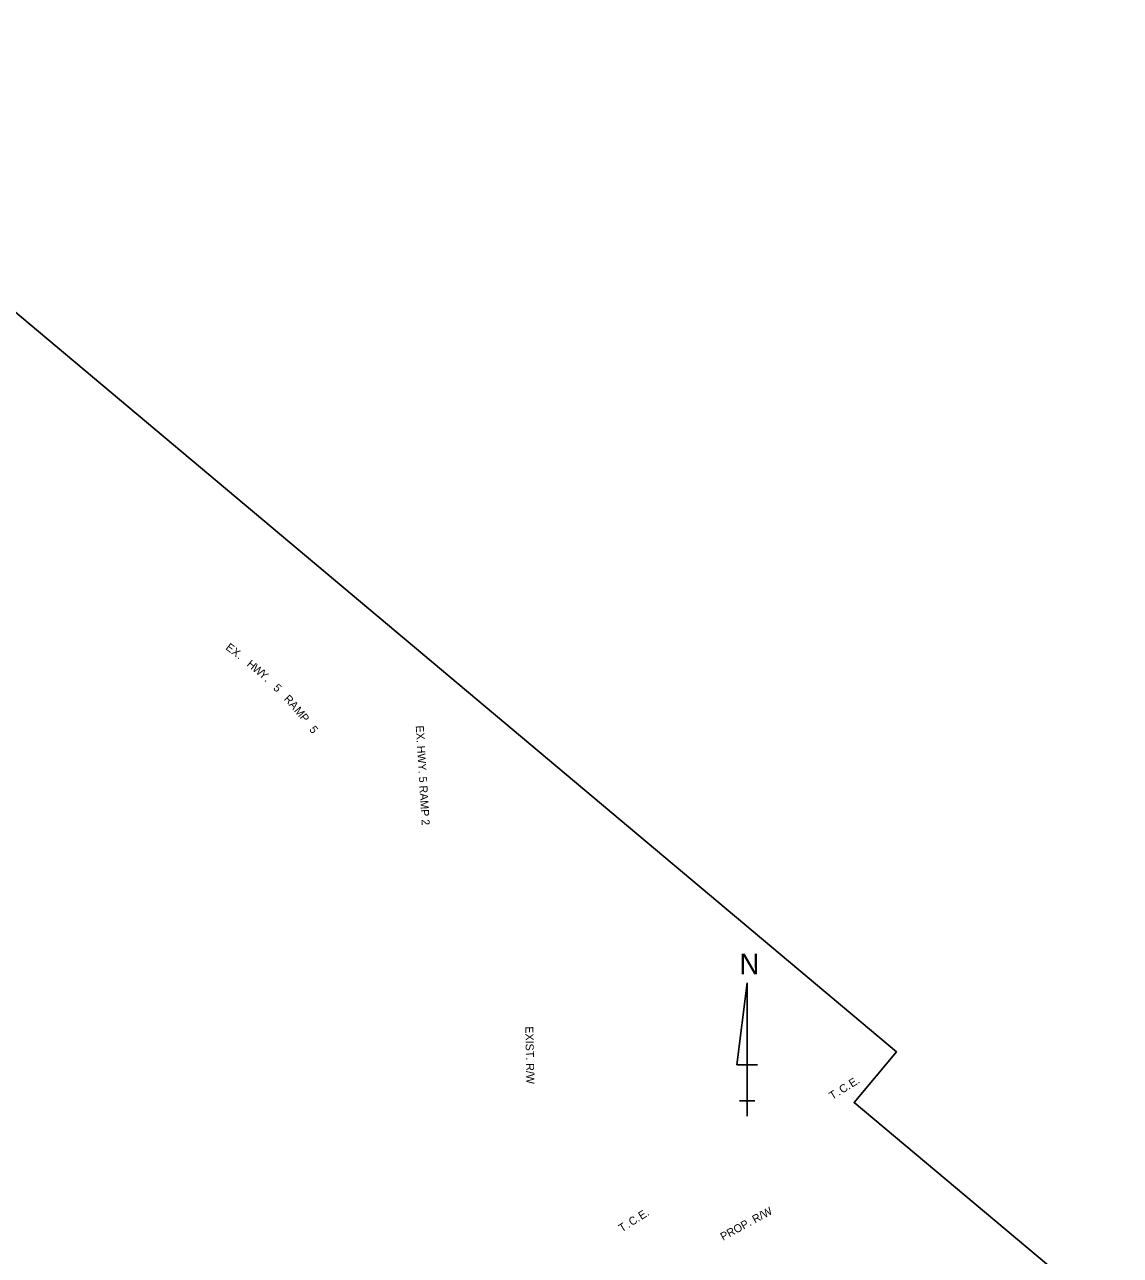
# Model space of a CAD drawing. Extents: x 1292584 to 1294434, y 222754 to 224578.
# Drawn here: x 1293518 to 1294340, y 223656 to 224578 of the extents above; entities that cross this region are included whole.
import ezdxf

# ---------------------------------------------------------------- set-up
doc = ezdxf.new("R2010")
doc.units = 0
for name, color, linetype in [('44', 7, 'Continuous'), ('Default', 7, 'Continuous'), ('R_Grid_Sta', 7, 'Continuous'), ('R_ROW', 7, 'Continuous'), ('R_Striping', 7, 'Continuous')]:
    doc.layers.add(name, color=color, linetype=linetype)

msp = doc.modelspace()

# ---------------------------------------------------------------- linework, layer by layer
at = {"layer": '44'}
msp.add_lwpolyline([(1292584.05, 223779.83), (1293254.04, 224578.3), (1294171.77, 223808.23), (1294139.92, 223770.28), (1294291.79, 223642.84), (1294281.83, 223630.97), (1294336.68, 223584.95), (1294241.87, 223471.95), (1294339.54, 223390), (1293806.17, 222754.35)], close=True, dxfattribs=at)
at = {"layer": 'R_Grid_Sta'}
for p, q in [((1294059.66, 223860.1), (1294051.96, 223798.56)), ((1294059.66, 223760.1), (1294059.66, 223860.1)), ((1294059.66, 223860.1), (1294059.66, 223783.17)), ((1294051.96, 223798.56), (1294067.35, 223798.56)), ((1294059.66, 223760.1), (1294059.66, 223783.17)), ((1294059.66, 223771.63), (1294053.89, 223771.63)), ((1294053.89, 223771.63), (1294065.43, 223771.63)), ((1294059.66, 223760.1), (1294059.66, 223771.63))]:
    msp.add_line(p, q, dxfattribs=at)

# ---------------------------------------------------------------- texts
at = {"layer": 'Default'}
for s, rotation, p in [('E', 323.67019, (1293668.26, 224110.33)), ('X', 321.85099, (1293672.58, 224107.12)), ('.', 321.85099, (1293677.12, 224103.56)), ('H', 320.47811, (1293684.13, 224098.03)), ('W', 320.47811, (1293688.28, 224094.6)), ('Y', 316.19848, (1293693.36, 224090.65)), ('.', 316.19848, (1293697.52, 224086.66)), ('5', 316.19848, (1293703.97, 224080.48)), ('R', 314.32365, (1293711.99, 224072.4)), ('A', 310.31304, (1293715.92, 224068.32)), ('M', 310.31304, (1293719.71, 224063.85)), ('P', 307.6643, (1293723.94, 224059.01)), ('5', 307.6643, (1293731.07, 224049.78))]:
    msp.add_text(s, height=6, rotation=rotation, dxfattribs=at).set_placement(p)
at = {"layer": 'R_Grid_Sta'}
msp.add_text('N', height=15.38, rotation=360, dxfattribs=at).set_placement((1294054.02, 223866.51))
at = {"layer": 'R_ROW'}
for s, rotation, p in [('EXIST. R/W', 271.19347, (1293893.37, 223827.34)), ('PROP. R/W', 28.60191, (1294041.67, 223666.61))]:
    msp.add_text(s, height=6, rotation=rotation, dxfattribs=at).set_placement(p)
at = {"layer": 'R_Striping'}
for s, rotation, p in [('EX. HWY. 5 RAMP 2', 273.49613, (1293811.24, 224052.73)), ('C', 32.15368, (1294131, 223776.82)), ('E', 32.15368, (1294138.28, 223781.39)), ('.', 32.15368, (1294142.84, 223784.26)), ('T', 32.15368, (1294123.56, 223772.14)), ('.', 32.15368, (1294128.52, 223775.26)), ('.', 32.15368, (1294135.8, 223779.83)), ('E', 32.15368, (1293980.44, 223682.18)), ('T', 32.15368, (1293965.73, 223672.93)), ('C', 32.15368, (1293973.17, 223677.6)), ('.', 32.15368, (1293977.97, 223680.62)), ('.', 32.15368, (1293985, 223685.04)), ('.', 32.15368, (1293970.69, 223676.04))]:
    msp.add_text(s, height=6, rotation=rotation, dxfattribs=at).set_placement(p)

doc.saveas('drawing.dxf')
